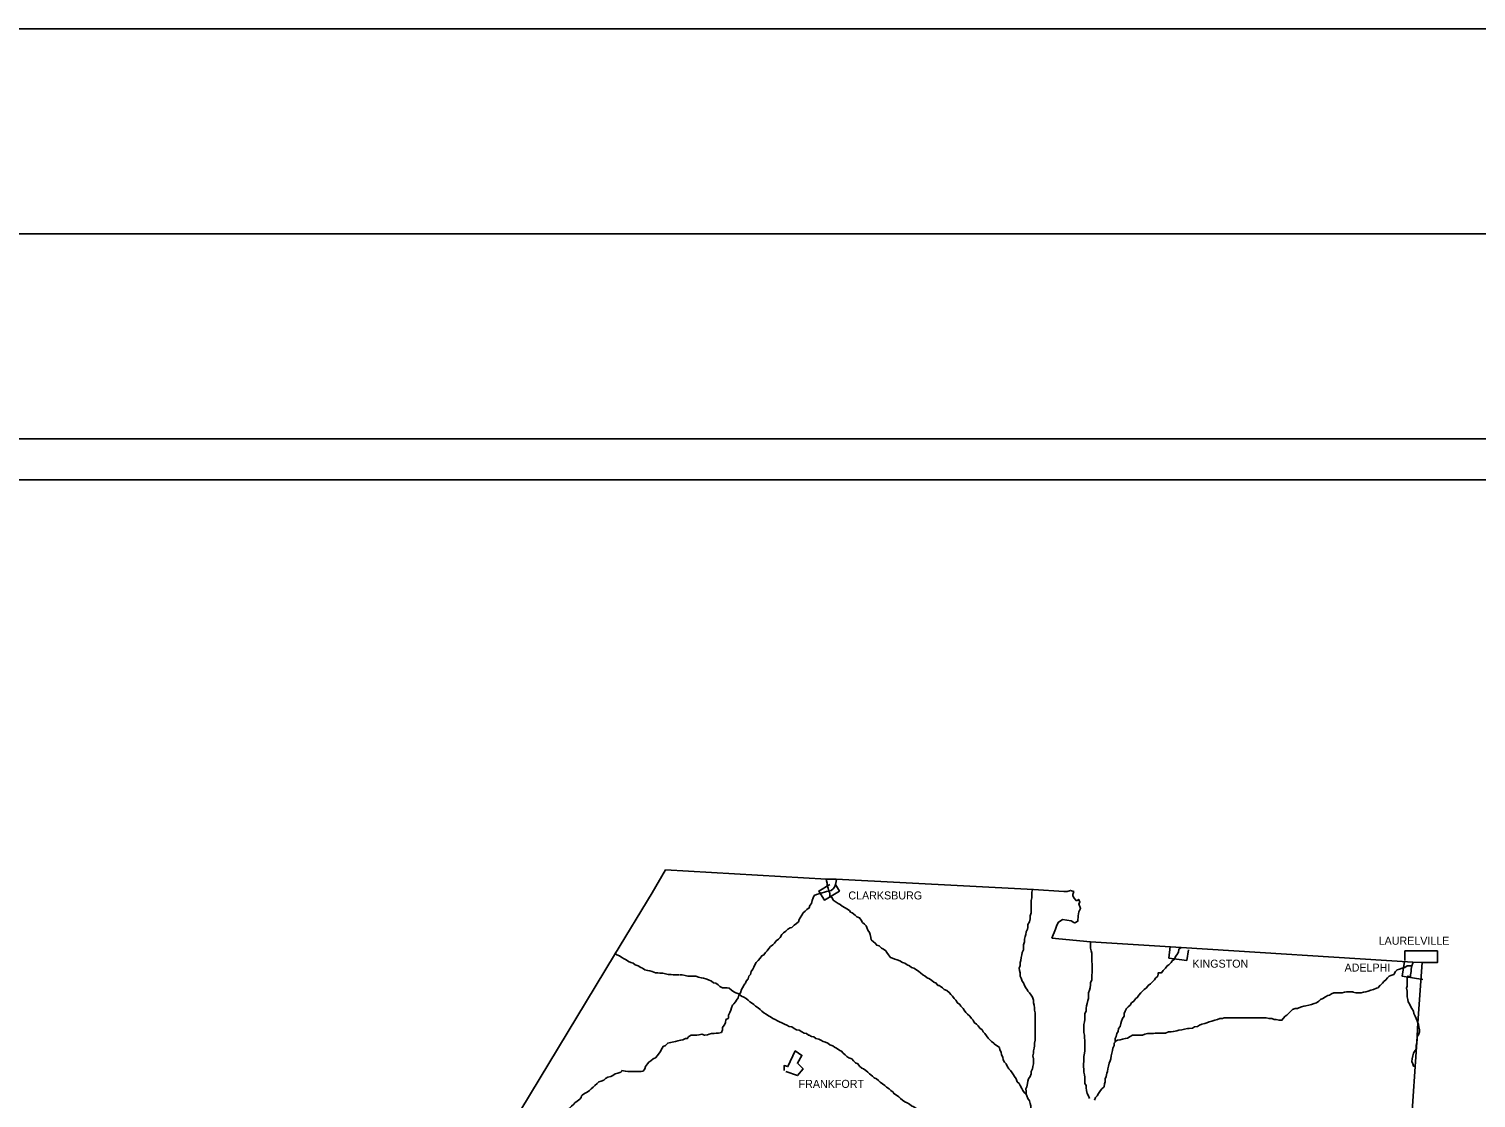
# Model space of a CAD drawing. Extents: x 0 to 40.2, y 0 to 22.
# Drawn here: x 3.548 to 7.075, y 19.393 to 22 of the extents above; entities that cross this region are included whole.
import ezdxf

# ---------------------------------------------------------------- set-up
doc = ezdxf.new("R2010")
doc.units = 0
for name, color, linetype in [('Default', 7, 'Continuous'), ('SH_Border', 7, 'Continuous'), ('SH_Cut_Line', 7, 'Continuous'), ('SH_Data', 7, 'Continuous')]:
    doc.layers.add(name, color=color, linetype=linetype)

msp = doc.modelspace()

# ---------------------------------------------------------------- linework, layer by layer
at = {"layer": 'Default'}
msp.add_line((6.9115, 19.723), (6.9115, 19.723), dxfattribs=at)
for points in [[(5.0995, 19.9493), (5.0668, 19.8934), (4.9754, 19.7421), (4.7232, 19.3249)], [(6.0416, 19.783), (6.0498, 19.8048), (6.0525, 19.8116), (6.0566, 19.8212), (6.0675, 19.828), (6.088, 19.8253), (6.0948, 19.8212), (6.0975, 19.8198), (6.1043, 19.8239), (6.1057, 19.8375), (6.107, 19.8471), (6.1111, 19.8553), (6.107, 19.8662), (6.1098, 19.8703), (6.107, 19.8771), (6.103, 19.8744), (6.1002, 19.8744), (6.0948, 19.8812), (6.092, 19.8866), (6.092, 19.8894), (6.0948, 19.8962), (6.0866, 19.8989), (6.0784, 19.8962), (6.0702, 19.8962), (5.9966, 19.9016), (5.5153, 19.9262), (5.4921, 19.9262), (5.0995, 19.9493)], [(5.3981, 19.8048), (5.4035, 19.8075), (5.4076, 19.8089), (5.4131, 19.8144), (5.4185, 19.8185), (5.424, 19.8225), (5.4253, 19.828), (5.4281, 19.8321), (5.4322, 19.8389), (5.4349, 19.8444), (5.4403, 19.8485), (5.4444, 19.8525), (5.4499, 19.8566), (5.4512, 19.8621), (5.4553, 19.8675), (5.4567, 19.8744), (5.4594, 19.8812), (5.4621, 19.8866), (5.4676, 19.8894), (5.4731, 19.8907), (5.4812, 19.8934), (5.4867, 19.8948), (5.4921, 19.8962), (5.4976, 19.8975), (5.4976, 19.8975)], [(5.5003, 19.9139), (5.4731, 19.8975), (5.4867, 19.8757), (5.5235, 19.8975), (5.514, 19.9139)], [(5.4976, 19.8975), (5.4962, 19.9044), (5.4935, 19.9112), (5.4935, 19.9166), (5.4921, 19.9221), (5.4908, 19.9262)], [(5.4976, 19.8975), (5.5031, 19.8989), (5.5085, 19.903), (5.5112, 19.9071), (5.514, 19.9139), (5.5153, 19.9207), (5.5167, 19.9262)], [(5.548, 19.8498), (5.5412, 19.8539), (5.5371, 19.8566), (5.5303, 19.8607), (5.5249, 19.8648), (5.5208, 19.8675), (5.5153, 19.8703), (5.5085, 19.8757), (5.5058, 19.8812), (5.5003, 19.8853), (5.5003, 19.8921), (5.4976, 19.8975)], [(5.9884, 19.8307), (5.9884, 19.8375), (5.9912, 19.8444), (5.9912, 19.8485), (5.9912, 19.8566), (5.9912, 19.8621), (5.9912, 19.8703), (5.9912, 19.8744), (5.9925, 19.8812), (5.9925, 19.888), (5.9925, 19.8948), (5.9939, 19.9016), (5.9939, 19.9016)], [(5.5889, 19.813), (5.5849, 19.8171), (5.5794, 19.8212), (5.5767, 19.8266), (5.5726, 19.8321), (5.5658, 19.8348), (5.5617, 19.8389), (5.5549, 19.8444), (5.5508, 19.8457), (5.548, 19.8498)], [(5.9816, 19.6562), (5.9775, 19.6617), (5.9748, 19.6671), (5.9721, 19.6739), (5.9693, 19.678), (5.9666, 19.6848), (5.9639, 19.6903), (5.9639, 19.6985), (5.9625, 19.7039), (5.9612, 19.7094), (5.9639, 19.7162), (5.9639, 19.723), (5.9653, 19.7285), (5.9666, 19.7353), (5.968, 19.7421), (5.9693, 19.7476), (5.9721, 19.7544), (5.9721, 19.7598), (5.9721, 19.7666), (5.9748, 19.7735), (5.9748, 19.7803), (5.9762, 19.7871), (5.9775, 19.7912), (5.9789, 19.798), (5.9816, 19.8048), (5.983, 19.8089), (5.983, 19.8157), (5.9871, 19.8225), (5.9884, 19.8294), (5.9884, 19.8307)], [(5.3204, 19.723), (5.3258, 19.7285), (5.3299, 19.7339), (5.334, 19.7394), (5.3394, 19.7421), (5.3435, 19.7476), (5.3476, 19.7516), (5.3517, 19.7571), (5.3558, 19.7626), (5.3613, 19.7666), (5.3653, 19.7707), (5.3694, 19.7762), (5.3749, 19.7803), (5.379, 19.7844), (5.3831, 19.7912), (5.3872, 19.7953), (5.3926, 19.7994), (5.3981, 19.8048), (5.3981, 19.8048)], [(5.6149, 19.7653), (5.6108, 19.7707), (5.6067, 19.7735), (5.6012, 19.7789), (5.5999, 19.7844), (5.5985, 19.7912), (5.5971, 19.7966), (5.593, 19.8021), (5.5903, 19.8089), (5.5889, 19.813)], [(5.683, 19.7217), (5.6776, 19.723), (5.6708, 19.7271), (5.6639, 19.7298), (5.6585, 19.7312), (5.653, 19.7339), (5.6476, 19.7353), (5.6435, 19.7421), (5.6394, 19.7476), (5.6367, 19.7516), (5.6312, 19.7557), (5.6258, 19.7585), (5.6203, 19.7639), (5.6149, 19.7653), (5.6149, 19.7653)], [(6.0416, 19.783), (6.1357, 19.7735), (6.3566, 19.7598), (6.921, 19.7244), (6.9442, 19.723)], [(6.133, 19.3917), (6.1302, 19.3985), (6.1275, 19.404), (6.1261, 19.4108), (6.1248, 19.4176), (6.1248, 19.4231), (6.122, 19.4285), (6.122, 19.4367), (6.122, 19.4435), (6.1207, 19.449), (6.1193, 19.4558), (6.1193, 19.4626), (6.118, 19.4694), (6.118, 19.4762), (6.1193, 19.4817), (6.1193, 19.4885), (6.1193, 19.494), (6.1207, 19.5021), (6.122, 19.5076), (6.122, 19.5144), (6.122, 19.5199), (6.122, 19.5267), (6.122, 19.5335), (6.1207, 19.539), (6.1207, 19.5458), (6.1193, 19.5526), (6.1193, 19.5594), (6.1193, 19.5662), (6.1193, 19.5717), (6.1207, 19.5785), (6.122, 19.5839), (6.122, 19.5921), (6.122, 19.5989), (6.1248, 19.6044), (6.1248, 19.6112), (6.1261, 19.618), (6.1275, 19.6235), (6.1289, 19.6303), (6.1302, 19.6358), (6.1302, 19.6439), (6.1302, 19.6494), (6.133, 19.6562), (6.1343, 19.6617), (6.1357, 19.6685), (6.1357, 19.6739), (6.1384, 19.6808), (6.1384, 19.6862), (6.1384, 19.693), (6.1398, 19.6985), (6.1398, 19.7067), (6.1398, 19.7121), (6.1398, 19.7189), (6.1384, 19.7257), (6.1384, 19.7326), (6.1384, 19.7394), (6.1384, 19.7462), (6.137, 19.7516), (6.1357, 19.7585), (6.1357, 19.7653), (6.1357, 19.7707), (6.1357, 19.7721), (6.1357, 19.7735)], [(6.302, 19.6985), (6.3088, 19.6985), (6.3129, 19.7039), (6.3184, 19.7094), (6.3225, 19.7148), (6.3266, 19.7176), (6.332, 19.723), (6.3347, 19.7271), (6.3402, 19.7312), (6.3429, 19.738), (6.3456, 19.7421), (6.3497, 19.7489), (6.3511, 19.7557), (6.3566, 19.7598), (6.3566, 19.7598)], [(6.3293, 19.7626), (6.3266, 19.7339), (6.3702, 19.7285), (6.3743, 19.7544)], [(4.9754, 19.7462), (4.9809, 19.7421), (4.9877, 19.7394), (4.9931, 19.7353), (4.9986, 19.7326), (5.004, 19.7298), (5.0095, 19.7257), (5.0149, 19.723), (5.0204, 19.7217), (5.0259, 19.7176), (5.0327, 19.7148), (5.0395, 19.7107), (5.0436, 19.7094), (5.049, 19.7053), (5.0559, 19.7039), (5.0613, 19.7026), (5.0668, 19.7012), (5.0749, 19.6985), (5.0804, 19.6985), (5.0858, 19.6971), (5.0927, 19.6971), (5.0995, 19.6957), (5.1063, 19.6944), (5.1131, 19.6944), (5.1186, 19.693), (5.1254, 19.693), (5.1322, 19.693), (5.1336, 19.693)], [(5.2944, 19.6726), (5.2958, 19.678), (5.3013, 19.6835), (5.3026, 19.6903), (5.3067, 19.6944), (5.3081, 19.7012), (5.3122, 19.7067), (5.3149, 19.7121), (5.3176, 19.7176), (5.3204, 19.723), (5.3204, 19.723)], [(5.7635, 19.6671), (5.7594, 19.6726), (5.7539, 19.6753), (5.7485, 19.6794), (5.743, 19.6835), (5.7376, 19.6862), (5.7321, 19.6903), (5.7267, 19.693), (5.7212, 19.6985), (5.7171, 19.7012), (5.7117, 19.7053), (5.7048, 19.7094), (5.6994, 19.7107), (5.6939, 19.7148), (5.6885, 19.7176), (5.683, 19.7217), (5.683, 19.7217)], [(6.9006, 19.7257), (6.8951, 19.6903), (6.9456, 19.6821)], [(6.9019, 19.7285), (6.9019, 19.7516), (6.981, 19.7516), (6.981, 19.723), (6.9442, 19.723)], [(6.9183, 19.7148), (6.921, 19.7217), (6.921, 19.7244)], [(6.9442, 19.723), (6.9333, 19.5758), (6.9306, 19.5294), (6.9265, 19.4694)], [(5.1349, 19.693), (5.1404, 19.693), (5.1472, 19.6917), (5.154, 19.6903), (5.1595, 19.6903), (5.1677, 19.6903), (5.1731, 19.6903), (5.1799, 19.6876), (5.1867, 19.6862), (5.1922, 19.6848), (5.1976, 19.6835), (5.2045, 19.6808), (5.2113, 19.678), (5.2167, 19.6739), (5.2222, 19.6726), (5.2276, 19.6685)], [(6.1957, 19.5308), (6.1957, 19.5376), (6.1984, 19.543), (6.1998, 19.5499), (6.2025, 19.5553), (6.2039, 19.5621), (6.2079, 19.5676), (6.2093, 19.5744), (6.2107, 19.5799), (6.2134, 19.5867), (6.2175, 19.5921), (6.2175, 19.5989), (6.2202, 19.6044), (6.2229, 19.6112), (6.227, 19.6153), (6.2325, 19.6194), (6.2352, 19.6249), (6.2407, 19.6289), (6.2448, 19.6344), (6.2502, 19.6385), (6.2529, 19.6439), (6.2584, 19.6494), (6.2625, 19.6535), (6.2666, 19.6576), (6.272, 19.6617), (6.2761, 19.6671), (6.2816, 19.6712), (6.2857, 19.6753), (6.2911, 19.6808), (6.2938, 19.6848), (6.2993, 19.6903), (6.3007, 19.6957), (6.3007, 19.6985), (6.302, 19.6985)], [(6.8419, 19.6671), (6.8474, 19.6726), (6.8501, 19.6767), (6.8556, 19.6808), (6.8597, 19.6862), (6.8637, 19.6903), (6.8678, 19.6917), (6.8747, 19.6944), (6.8787, 19.7012), (6.8828, 19.7053), (6.8883, 19.7067), (6.8951, 19.7094), (6.9019, 19.7107), (6.9074, 19.7148), (6.9128, 19.7148), (6.9183, 19.7148)], [(6.9333, 19.5758), (6.9319, 19.5812), (6.9292, 19.5867), (6.9265, 19.5921), (6.9237, 19.5989), (6.9224, 19.6044), (6.9183, 19.6112), (6.9156, 19.6167), (6.9128, 19.6221), (6.9101, 19.6276), (6.9087, 19.633), (6.9074, 19.6398), (6.9074, 19.6467), (6.9074, 19.6535), (6.906, 19.6603), (6.9074, 19.6658), (6.9074, 19.6726), (6.9074, 19.678), (6.9074, 19.6848), (6.9087, 19.6903), (6.9156, 19.6876), (6.9156, 19.693), (6.9169, 19.7012), (6.9169, 19.7067), (6.9183, 19.7148), (6.9183, 19.7148)], [(5.2276, 19.6685), (5.2317, 19.6644), (5.2385, 19.6617), (5.244, 19.6617), (5.2495, 19.6617), (5.2549, 19.6603), (5.2604, 19.6562), (5.2658, 19.6521), (5.2713, 19.6494), (5.2781, 19.6467), (5.2795, 19.6453)], [(5.2795, 19.6453), (5.2822, 19.6494), (5.2849, 19.6576), (5.2876, 19.6617), (5.2917, 19.6685), (5.2931, 19.6712), (5.2944, 19.6726)], [(5.8998, 19.5267), (5.8944, 19.5308), (5.8903, 19.5349), (5.8862, 19.539), (5.8821, 19.5444), (5.878, 19.5499), (5.8739, 19.554), (5.8712, 19.5594), (5.8657, 19.5635), (5.8616, 19.569), (5.8575, 19.573), (5.8521, 19.5771), (5.8494, 19.5826), (5.8453, 19.5867), (5.8412, 19.5921), (5.8357, 19.5976), (5.8316, 19.6017), (5.8275, 19.6071), (5.8248, 19.6112), (5.8194, 19.6167), (5.8166, 19.6208), (5.8112, 19.6249), (5.8071, 19.6317), (5.803, 19.6358), (5.7989, 19.6412), (5.7948, 19.6453), (5.7921, 19.6494), (5.7853, 19.6548), (5.7785, 19.6576), (5.7744, 19.6617), (5.7689, 19.6658), (5.7662, 19.6671), (5.7635, 19.6671)], [(6.0007, 19.543), (6.0007, 19.5499), (6.0007, 19.5567), (6.0007, 19.5621), (6.0007, 19.569), (6.0007, 19.5758), (6.0007, 19.5812), (6.0007, 19.588), (6.0007, 19.5949), (6.0007, 19.6003), (5.9993, 19.6071), (5.9993, 19.6126), (5.998, 19.6194), (5.9966, 19.6249), (5.9966, 19.6317), (5.9939, 19.6385), (5.9912, 19.6439), (5.9871, 19.6494), (5.983, 19.6535), (5.9816, 19.6562)], [(6.6429, 19.6126), (6.6497, 19.6153), (6.6551, 19.6167), (6.6606, 19.618), (6.6674, 19.6194), (6.6742, 19.6208), (6.681, 19.6235), (6.6865, 19.6249), (6.692, 19.6289), (6.696, 19.633), (6.7015, 19.6358), (6.7083, 19.6398), (6.7138, 19.6426), (6.7179, 19.6439), (6.7233, 19.6467), (6.7288, 19.6494), (6.7356, 19.6494), (6.7424, 19.6494), (6.7492, 19.6494), (6.7547, 19.6508), (6.7601, 19.6521), (6.7683, 19.6521), (6.7751, 19.6521), (6.7751, 19.6508)], [(6.7751, 19.6508), (6.7819, 19.6494), (6.7888, 19.6494), (6.7956, 19.6494), (6.801, 19.6508), (6.8065, 19.6521), (6.8119, 19.6535), (6.8188, 19.6562), (6.8256, 19.6576), (6.8324, 19.6603), (6.8365, 19.6617), (6.8406, 19.6671), (6.8419, 19.6671)], [(5.2535, 19.588), (5.2535, 19.5949), (5.2563, 19.6017), (5.259, 19.6071), (5.2604, 19.6126), (5.2631, 19.6194), (5.2658, 19.6221)], [(5.2658, 19.6221), (5.2699, 19.6276), (5.2726, 19.6317), (5.2767, 19.6371), (5.2781, 19.6439), (5.2795, 19.6453)], [(5.2795, 19.6453), (5.2849, 19.6412), (5.2904, 19.6385), (5.2958, 19.6358), (5.3013, 19.6317), (5.3054, 19.6276), (5.3094, 19.6249), (5.3149, 19.6208), (5.319, 19.6167), (5.3258, 19.6126), (5.3299, 19.6085), (5.334, 19.6044), (5.3394, 19.6003), (5.3449, 19.5976), (5.3503, 19.5935), (5.3558, 19.5908), (5.3613, 19.5867), (5.3667, 19.5839), (5.3722, 19.5812), (5.3776, 19.5785), (5.3831, 19.5758), (5.3899, 19.573), (5.3953, 19.5703), (5.4008, 19.5676), (5.4076, 19.5662), (5.4131, 19.5621), (5.4185, 19.5594), (5.4253, 19.558), (5.4322, 19.554), (5.4376, 19.5512), (5.4431, 19.5499), (5.4485, 19.5458), (5.4499, 19.5458)], [(6.4629, 19.588), (6.4684, 19.588), (6.4738, 19.588), (6.4806, 19.588), (6.4874, 19.588), (6.4943, 19.588), (6.5011, 19.588), (6.5079, 19.588), (6.5133, 19.588), (6.5215, 19.588), (6.527, 19.588), (6.5338, 19.588), (6.5393, 19.588), (6.5461, 19.588), (6.5529, 19.588), (6.5583, 19.588), (6.5638, 19.588), (6.5706, 19.5867), (6.5774, 19.5867), (6.5829, 19.5839), (6.5883, 19.5839), (6.5952, 19.5826), (6.602, 19.5826), (6.6047, 19.5867), (6.6101, 19.5921), (6.6142, 19.5949), (6.6197, 19.6003), (6.6238, 19.6044), (6.6279, 19.6085), (6.6347, 19.6112), (6.6401, 19.6112), (6.6429, 19.6126)], [(5.2181, 19.5499), (5.2236, 19.5512), (5.229, 19.5512), (5.2358, 19.5526), (5.2385, 19.5594), (5.2385, 19.5649), (5.2426, 19.5703), (5.2454, 19.5758), (5.2467, 19.5839), (5.2522, 19.5867), (5.2535, 19.588)], [(6.1957, 19.5308), (6.2011, 19.5335), (6.2079, 19.5349), (6.2134, 19.5362), (6.2202, 19.5376), (6.2257, 19.539), (6.2325, 19.543), (6.2379, 19.5458), (6.2434, 19.5458), (6.2502, 19.5458), (6.2543, 19.5458), (6.2625, 19.5458), (6.2679, 19.5485), (6.2747, 19.5499), (6.2816, 19.5499), (6.2884, 19.5499), (6.2938, 19.5512), (6.3007, 19.5512), (6.3075, 19.5512), (6.3129, 19.5512), (6.3184, 19.5512), (6.3252, 19.554), (6.332, 19.554), (6.3375, 19.5553), (6.3456, 19.5567), (6.3511, 19.558), (6.3579, 19.5594), (6.3647, 19.5608), (6.3716, 19.5621), (6.3756, 19.5621), (6.3838, 19.5635), (6.3893, 19.5662), (6.3961, 19.5676), (6.4015, 19.5703), (6.407, 19.573), (6.4138, 19.5744), (6.4193, 19.5758), (6.4247, 19.5785), (6.4315, 19.5799), (6.4384, 19.5826), (6.4452, 19.5839), (6.4506, 19.5867), (6.4574, 19.5867), (6.4615, 19.588), (6.4629, 19.588)], [(5.1527, 19.5376), (5.1567, 19.543), (5.1622, 19.5458), (5.1704, 19.5458), (5.1758, 19.5458), (5.1813, 19.5471), (5.1881, 19.5485), (5.1949, 19.5458), (5.2017, 19.5471), (5.2058, 19.5485), (5.2113, 19.5499), (5.2167, 19.5499), (5.2181, 19.5499)], [(5.4499, 19.5458), (5.4553, 19.543), (5.4608, 19.5417), (5.4662, 19.5376), (5.4731, 19.5362), (5.4785, 19.5335), (5.484, 19.5308), (5.4894, 19.5294), (5.4949, 19.5267), (5.5003, 19.5226), (5.5071, 19.5199), (5.5112, 19.5171), (5.5167, 19.5144), (5.5221, 19.5103), (5.5262, 19.5076), (5.5276, 19.5076)], [(5.9789, 19.4026), (5.9789, 19.4094), (5.9775, 19.4149), (5.9802, 19.4203), (5.9816, 19.4285), (5.983, 19.434), (5.9843, 19.4394), (5.9884, 19.4449), (5.9912, 19.4517), (5.9912, 19.4572), (5.9939, 19.464), (5.9952, 19.4694), (5.9966, 19.4762), (5.9966, 19.4817), (5.9966, 19.4885), (5.9952, 19.4953), (5.9966, 19.5021), (5.9966, 19.5076), (5.998, 19.5144), (5.9993, 19.5199), (5.9993, 19.5267), (6.0007, 19.5335), (6.0007, 19.5376), (6.0007, 19.543)], [(6.9306, 19.5294), (6.9319, 19.5349), (6.9319, 19.543), (6.9346, 19.5471), (6.9374, 19.554), (6.9374, 19.5594), (6.936, 19.5662), (6.9346, 19.573), (6.9333, 19.5758), (6.9333, 19.5758)], [(4.9931, 19.4599), (5.0013, 19.4585), (5.0081, 19.4572), (5.0149, 19.4572), (5.0204, 19.4572), (5.0259, 19.4572), (5.034, 19.4572), (5.0395, 19.4572), (5.0449, 19.4585), (5.049, 19.464), (5.0504, 19.4694), (5.0559, 19.4762), (5.0586, 19.4803), (5.064, 19.4831), (5.0695, 19.4885), (5.0749, 19.4912), (5.0804, 19.4967), (5.0845, 19.5021), (5.0872, 19.5062), (5.0886, 19.5103)], [(5.0886, 19.5103), (5.0913, 19.5144), (5.094, 19.5185), (5.0995, 19.5212), (5.1049, 19.5267), (5.1118, 19.528), (5.1158, 19.5294), (5.124, 19.5308), (5.1295, 19.5321), (5.1363, 19.5335), (5.1417, 19.5349), (5.1486, 19.5376), (5.1527, 19.5376), (5.1527, 19.5376)], [(5.3926, 19.4572), (5.4212, 19.4476), (5.4349, 19.464), (5.4212, 19.4776), (5.4322, 19.4967), (5.4158, 19.5076), (5.3981, 19.4694), (5.3885, 19.4721), (5.3885, 19.4599)], [(5.5276, 19.5076), (5.533, 19.5021), (5.5371, 19.4981), (5.5412, 19.494), (5.5467, 19.4912), (5.5535, 19.4885), (5.5576, 19.4831), (5.563, 19.479), (5.5685, 19.4762), (5.5726, 19.4708), (5.578, 19.4653), (5.5821, 19.464), (5.5876, 19.4599), (5.593, 19.4558), (5.5971, 19.4517), (5.6039, 19.4462), (5.608, 19.4422), (5.6135, 19.4394), (5.6189, 19.4353), (5.623, 19.4312), (5.6285, 19.4272), (5.6339, 19.4231), (5.638, 19.419), (5.6448, 19.4149), (5.6489, 19.4108), (5.6544, 19.4067), (5.6558, 19.404), (5.6558, 19.404)], [(5.9789, 19.4026), (5.9748, 19.4053), (5.9707, 19.4108), (5.968, 19.4162), (5.9639, 19.4231), (5.9612, 19.4285), (5.9571, 19.4326), (5.9543, 19.4394), (5.9503, 19.4449), (5.9475, 19.449), (5.9448, 19.4544), (5.9407, 19.4599), (5.9366, 19.464), (5.9325, 19.4708), (5.9298, 19.4762), (5.9257, 19.4803), (5.923, 19.4858), (5.9216, 19.4926), (5.9189, 19.4981), (5.9175, 19.5049), (5.9148, 19.5103), (5.9134, 19.5158), (5.908, 19.5199), (5.9012, 19.524), (5.9012, 19.5253), (5.8998, 19.5267)], [(6.1452, 19.3876), (6.148, 19.3944), (6.152, 19.3985), (6.1548, 19.404), (6.1602, 19.4108), (6.1629, 19.4149), (6.1684, 19.4203), (6.1698, 19.4272), (6.1711, 19.4326), (6.1711, 19.4394), (6.1739, 19.4449), (6.1752, 19.4531), (6.1766, 19.4572), (6.1779, 19.464), (6.1793, 19.4708), (6.1807, 19.4776), (6.1834, 19.4831), (6.1848, 19.4885), (6.1861, 19.4953), (6.1875, 19.5021), (6.1889, 19.509), (6.1902, 19.5144), (6.1929, 19.5212), (6.1929, 19.5267), (6.1957, 19.5294), (6.1957, 19.5308)], [(6.9265, 19.4694), (6.9224, 19.4708), (6.921, 19.4762), (6.9183, 19.4817), (6.9196, 19.4885), (6.921, 19.4953), (6.9224, 19.5021), (6.9251, 19.5062), (6.9292, 19.5117), (6.9292, 19.5171), (6.9292, 19.5212), (6.9306, 19.5267), (6.9306, 19.5294)], [(4.8963, 19.3999), (4.9018, 19.404), (4.9086, 19.4067), (4.9141, 19.4108), (4.9181, 19.4149), (4.9236, 19.419), (4.9277, 19.4231), (4.9331, 19.4285), (4.9372, 19.4326), (4.9427, 19.434), (4.9495, 19.4367), (4.9536, 19.4408), (4.959, 19.4435), (4.9659, 19.4449), (4.9713, 19.4476), (4.9768, 19.4517), (4.9836, 19.4531), (4.9904, 19.4558), (4.9931, 19.4585), (4.9931, 19.4599), (4.9931, 19.4599)], [(6.9265, 19.4694), (6.9156, 19.3004), (6.8897, 18.9131), (6.8787, 18.7414), (6.8624, 18.545)], [(5.6558, 19.404), (5.6626, 19.3999), (5.668, 19.3958), (5.6721, 19.3917), (5.6776, 19.3876), (5.683, 19.3835), (5.6885, 19.3808), (5.6939, 19.3781), (5.6994, 19.374), (5.7048, 19.3713), (5.7103, 19.3672), (5.7157, 19.3658), (5.7212, 19.3631), (5.7267, 19.3617), (5.7321, 19.359), (5.7389, 19.3563), (5.7444, 19.3549), (5.7512, 19.3535), (5.758, 19.3535), (5.7621, 19.3522), (5.7621, 19.3522)], [(5.9939, 19.3413), (5.9925, 19.3494), (5.9912, 19.3549), (5.9912, 19.3617), (5.9898, 19.3672), (5.9898, 19.374), (5.9884, 19.3794), (5.9871, 19.3863), (5.983, 19.3917), (5.9802, 19.3985), (5.9789, 19.4026), (5.9789, 19.4026)], [(4.8063, 19.3167), (4.8104, 19.3222), (4.8173, 19.3249), (4.8213, 19.3304), (4.8268, 19.3344), (4.8295, 19.3385), (4.8363, 19.3426), (4.8404, 19.3467), (4.8459, 19.3508), (4.8513, 19.3549), (4.8541, 19.359), (4.8609, 19.3644), (4.865, 19.3672), (4.8704, 19.3726), (4.8759, 19.3781), (4.8786, 19.3808), (4.8841, 19.3849), (4.8909, 19.3903), (4.8936, 19.3944), (4.895, 19.3985), (4.8963, 19.3999)]]:
    msp.add_lwpolyline(points, dxfattribs=at)
at = {"layer": 'SH_Border'}
msp.add_lwpolyline([(1.5, 21.5), (33.5, 21.5), (33.5, 0.5), (1.5, 0.5)], close=True, dxfattribs=at)
at = {"layer": 'SH_Cut_Line'}
msp.add_lwpolyline([(0, 0), (34, 0), (34, 22), (0, 22)], close=True, dxfattribs=at)
at = {"layer": 'SH_Data'}
for p, q in [((2, 21), (9, 21)), ((2.1, 20.9), (8.9, 20.9))]:
    msp.add_line(p, q, dxfattribs=at)

# ---------------------------------------------------------------- texts
at = {"layer": 'Default'}
for s, height, p in [('CLARKSBURG', 0.0195, (5.5453, 19.8771)), ('LAURELVILLE', 0.019502, (6.8378, 19.7666)), ('KINGSTON', 0.0195, (6.3838, 19.7107)), ('ADELPHI', 0.0195, (6.7547, 19.7012)), ('FRANKFORT', 0.0195, (5.424, 19.4176))]:
    msp.add_text(s, height=height, dxfattribs=at).set_placement(p)

doc.saveas('drawing.dxf')
